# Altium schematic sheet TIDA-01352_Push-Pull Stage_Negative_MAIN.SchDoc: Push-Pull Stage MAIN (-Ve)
size 431 x 279 mm; Date: Not shown in title block; ApprovedBy: Not shown in title block; CheckedBy: Not shown in title block; Author: Not shown in title block; CompanyName: Not shown in title block; DrawnBy: Sanjay Pithadia; Engineer: Sanjay Pithadia; Organization: Not shown in title block; Address1: Not shown in title block; Address2: Not shown in title block; Address3: Not shown in title block; Address4: Not shown in title block; DocumentNumber: 1; Revision: Use project parameter SCH_Rev; SheetNumber: 3; SheetTotal: 9; PageSetup: Record=PageOptions¦CenterHorizontal=True¦CenterVertical=True¦PrintScale=1.00¦XCorrection=1.00¦YCorrection=1.00¦PrintKind=0¦BorderSize=5000000¦LeftOffset=0¦BottomOffset=0¦Orientation=2¦PaperLength=1000¦PaperWidth=1000¦Scale=100¦PaperSource=15¦PrintQuality=600¦MediaType=1¦DitherType=10¦PaperKind=Letter¦PrintScaleMode=1
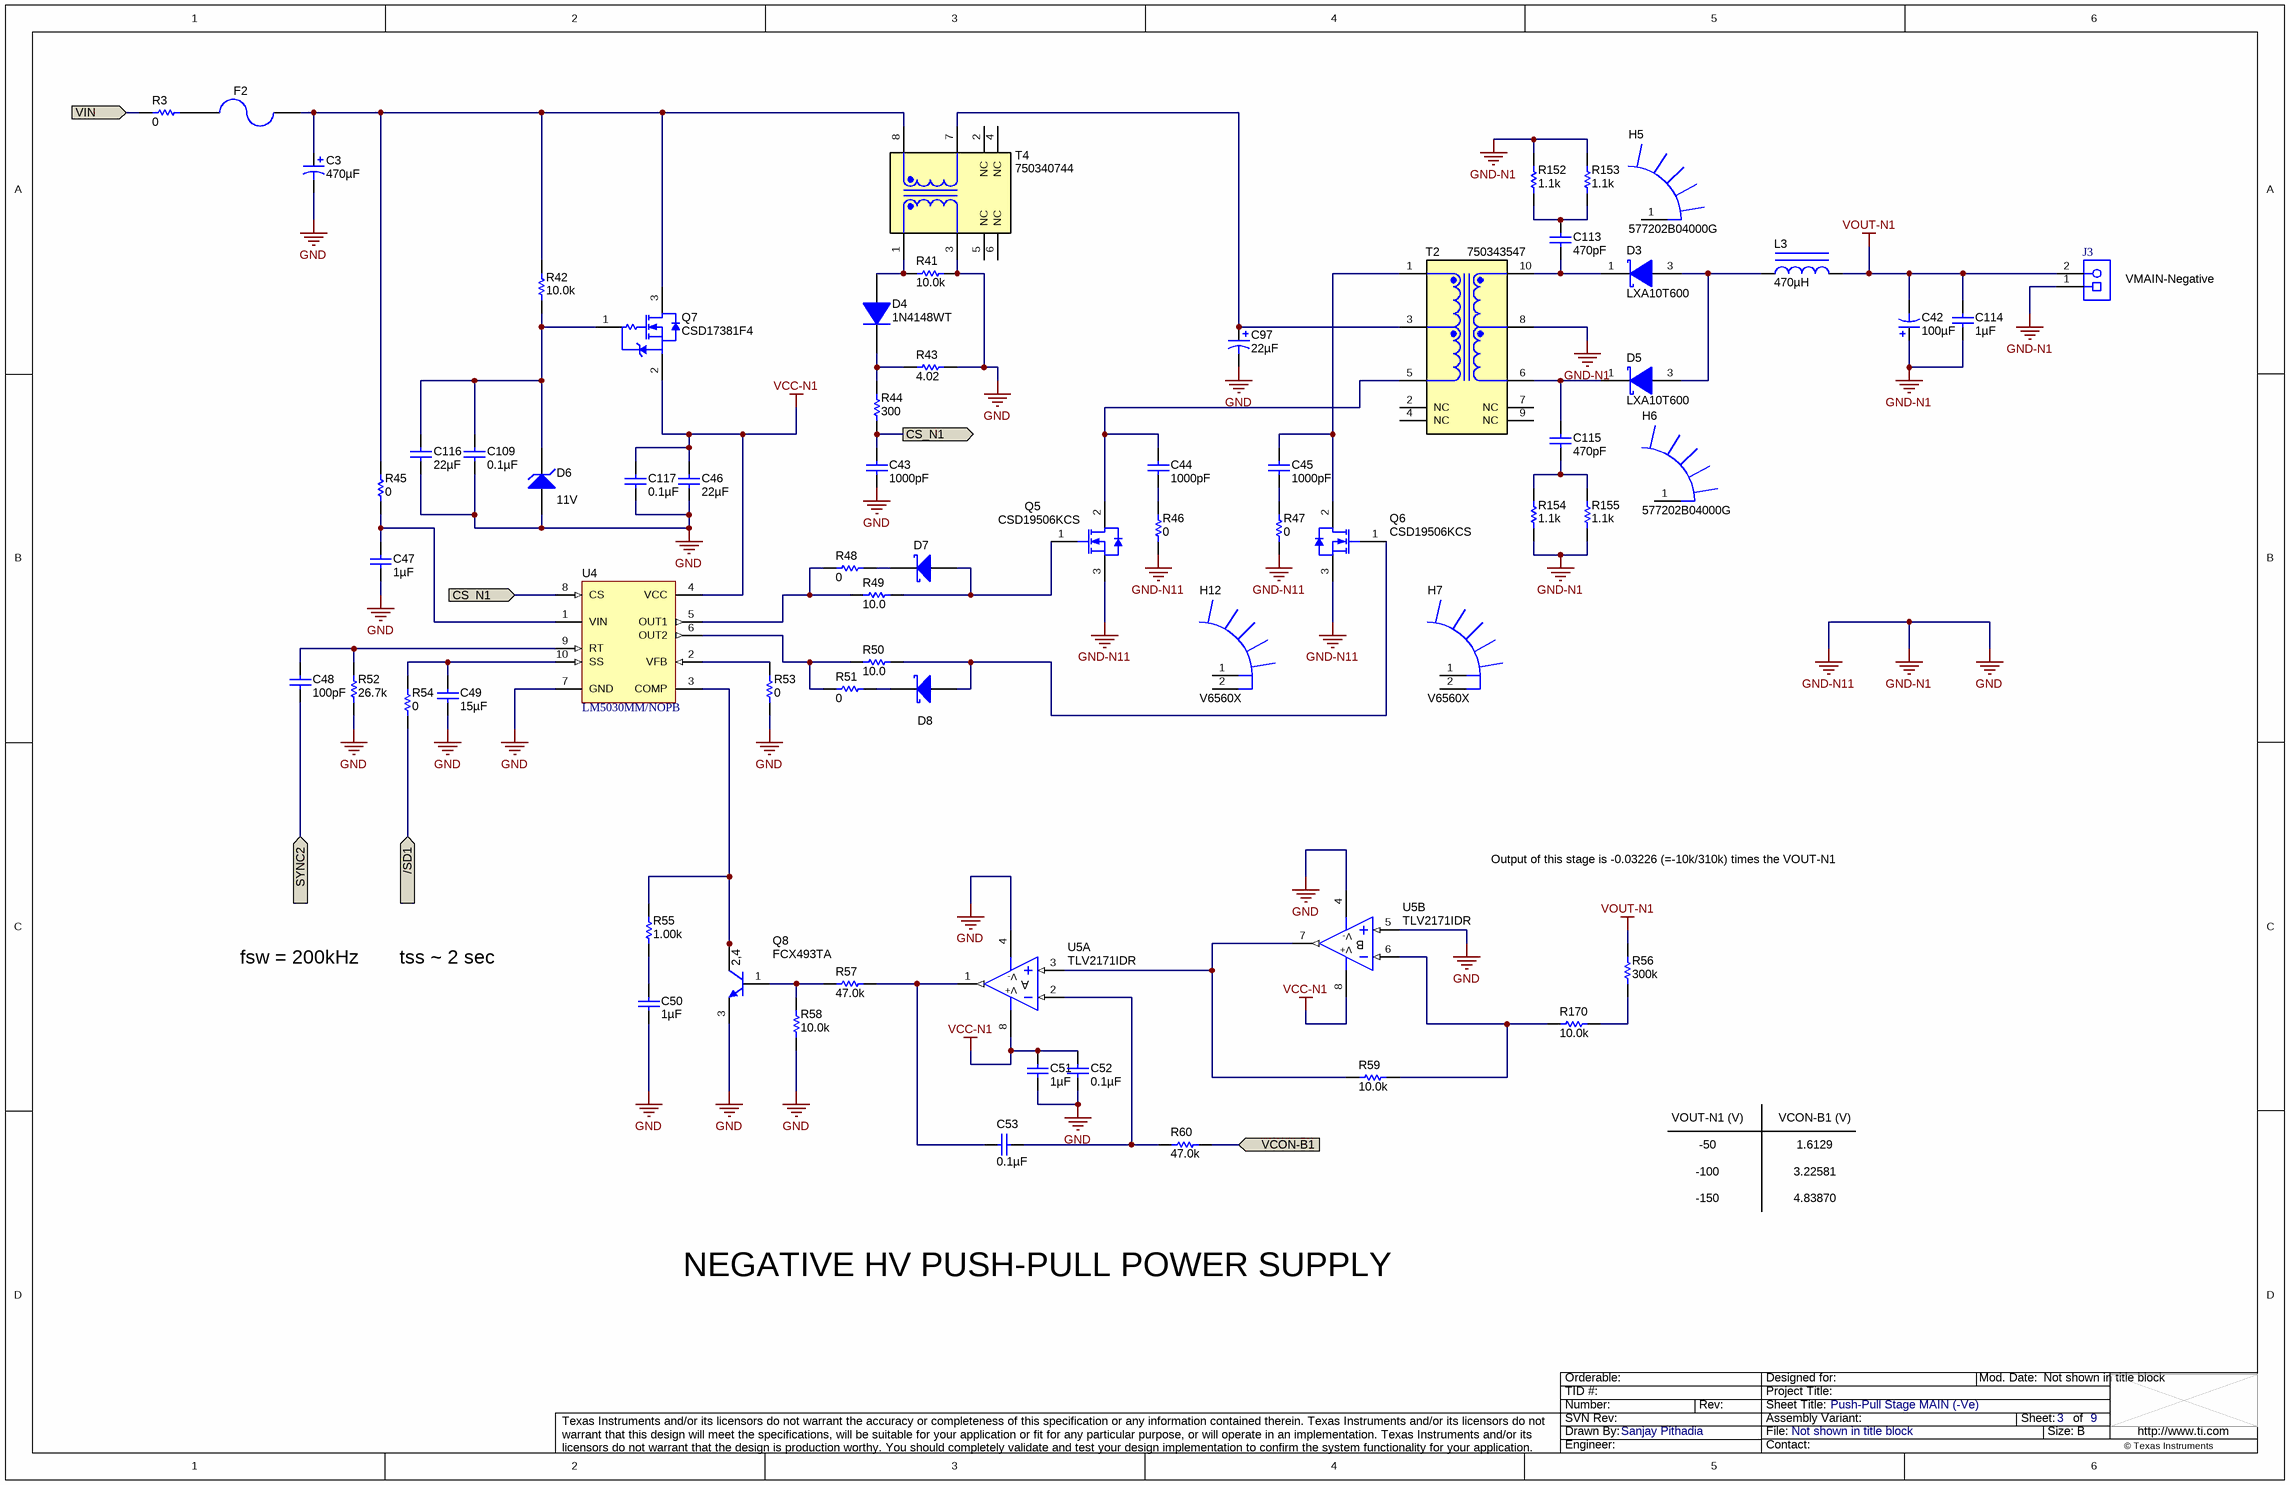
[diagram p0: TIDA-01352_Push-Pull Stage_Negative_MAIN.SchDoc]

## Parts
C3  ValueDisplayed: 470µF  [WCAP-ATLI_1300x3000]  (hidden comment: 860080778023)
C42  ValueDisplayed: 100µF  [Nichicon_2000x3000_Snap]  (hidden comment: LLS2G101MELY)
C43  ValueDisplayed: 1000pF  [0603]  (hidden comment: GRM188R71E102KA01D)
C44  ValueDisplayed: 1000pF  [0603]  (hidden comment: GRM188R71E102KA01D)
C45  ValueDisplayed: 1000pF  [0603]  (hidden comment: GRM188R71E102KA01D)
C46  ValueDisplayed: 22µF  [1210_280]  (hidden comment: 12103D226MAT2A)
C47  ValueDisplayed: 1µF  [0805_HV]  (hidden comment: 08055C105KAT2A)
C48  ValueDisplayed: 100pF  [0603]  (hidden comment: 06035A101FAT2A)
C49  ValueDisplayed: 15µF  [0805_HV]  (hidden comment: C2012X5R1V156M125AC)
C50  ValueDisplayed: 1µF  [0603]  (hidden comment: GMK107BJ105KA-T)
C51  ValueDisplayed: 1µF  [0805_HV]  (hidden comment: 08055C105KAT2A)
C52  ValueDisplayed: 0.1µF  [0603]  (hidden comment: 06035C104KAT2A)
C53  ValueDisplayed: 0.1µF  [0603]  (hidden comment: 06035C104KAT2A)
C97  ValueDisplayed: 22µF  [SM_RADIAL_E]  (hidden comment: EEE-FC1H220P)
C109  ValueDisplayed: 0.1µF  [0603]  (hidden comment: 06035C104KAT2A)
C113  ValueDisplayed: 470pF  [1206]  (hidden comment: VJ1206Y471KBEAT4X)
C114  ValueDisplayed: 1µF  [2220_200]  (hidden comment: GRM55DR72E105KW01L)
C115  ValueDisplayed: 470pF  [1206]  (hidden comment: VJ1206Y471KBEAT4X)
C116  ValueDisplayed: 22µF  [1210_280]  (hidden comment: 12103D226MAT2A)
C117  ValueDisplayed: 0.1µF  [0603]  (hidden comment: 06035C104KAT2A)
D3  LXA10T600  [TO-220AC]
D4  1N4148WT  [Fairchild_SOD-523F]
D5  LXA10T600  [TO-220AC]
D6  value 11V  [SMA]  (hidden comment: 1SMA5926BT3G)
D7  PMEG1030EJ,115  [SOD-323F]  (value not drawn)
D8  PMEG1030EJ,115  [SOD-323F]  (value not drawn)
F2  0678L9150-02  [Fuse_0678L]  (value not drawn)
H5  577202B04000G  [Aavid_577202B04000G]
H6  577202B04000G  [Aavid_577202B04000G]
H7  V6560X  [ASMN_V6560X]
H12  V6560X  [ASMN_V6560X]
J3  1727010  [PhoenixConact_1727010]  (value not drawn)
L3  ValueDisplayed: 470µH  [1447440C]  (hidden comment: 1447440C)
Q5  CSD19506KCS  [KCS0003B]
Q6  CSD19506KCS  [KCS0003B]
Q7  CSD17381F4  [YJC0003A]
Q8  FCX493TA  [SOT-89-3]
R3  ValueDisplayed: 0  [5108]  (hidden comment: 5108)
R41  ValueDisplayed: 10.0k  [0603]  (hidden comment: CRCW060310K0FKEA)
R42  ValueDisplayed: 10.0k  [0603]  (hidden comment: CRCW060310K0FKEA)
R43  ValueDisplayed: 4.02  [0805_HV]  (hidden comment: CRCW08054R02FKEA)
R44  ValueDisplayed: 300  [0603]  (hidden comment: RC0603FR-07300RL)
R45  ValueDisplayed: 0  [0603]  (hidden comment: CRCW06030000Z0EA)
R46  ValueDisplayed: 0  [0603]  (hidden comment: CRCW06030000Z0EA)
R47  ValueDisplayed: 0  [0603]  (hidden comment: CRCW06030000Z0EA)
R48  ValueDisplayed: 0  [0603]  (hidden comment: CRCW06030000Z0EA)
R49  ValueDisplayed: 10.0  [0603]  (hidden comment: CRCW060310R0FKEA)
R50  ValueDisplayed: 10.0  [0603]  (hidden comment: CRCW060310R0FKEA)
R51  ValueDisplayed: 0  [0603]  (hidden comment: CRCW06030000Z0EA)
R52  ValueDisplayed: 26.7k  [0603]  (hidden comment: CRCW060326K7FKEA)
R53  ValueDisplayed: 0  [0603]  (hidden comment: CRCW06030000Z0EA)
R54  ValueDisplayed: 0  [0603]  (hidden comment: CRCW06030000Z0EA)
R55  ValueDisplayed: 1.00k  [0603]  (hidden comment: CRCW06031K00FKEA)
R56  ValueDisplayed: 300k  [1206]  (hidden comment: RC1206FR-07300KL)
R57  ValueDisplayed: 47.0k  [0603]  (hidden comment: RC0603FR-0747KL)
R58  ValueDisplayed: 10.0k  [0603]  (hidden comment: CRCW060310K0FKEA)
R59  ValueDisplayed: 10.0k  [1206]  (hidden comment: CRCW120610K0FKEA)
R60  ValueDisplayed: 47.0k  [0603]  (hidden comment: RC0603FR-0747KL)
R152  ValueDisplayed: 1.1k  [PR01]  (hidden comment: PR01000101101JR500)
R153  ValueDisplayed: 1.1k  [PR01]  (hidden comment: PR01000101101JR500)
R154  ValueDisplayed: 1.1k  [PR01]  (hidden comment: PR01000101101JR500)
R155  ValueDisplayed: 1.1k  [PR01]  (hidden comment: PR01000101101JR500)
R170  ValueDisplayed: 10.0k  [1206]  (hidden comment: CRCW120610K0FKEA)
T2  750343547  [Wurth_750343473]
T4  750340744  [Wurth_750340744]
U4  LM5030MM/NOPB  [MUB10A_N]
U5  TLV2171IDR  [D0008A_N]  (parts A,B of 2)

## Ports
/SD1 (in), CS_N1 (in), CS_N1 (out), SYNC2 (in), VCON-B1 (in), VIN (in)

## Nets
GND: C3.2(-) C42.1(+) C43.2 C46.2 C47.2 C49.2 C50.2 C51.2 C52.2 C97.2(-) C109.2 C114.2 C116.2 C117.2 D6.2(A) J3.1 Q5.3(S) Q6.3(S) Q8.3(E) R41.1 R43.2 R46.2 R47.2 R52.1 R53.1 R58.1 R152.2 R153.2 R154.1 R155.1 T2.8 T4.3 U4.7(GND) U5.4(V-) U5.5(IN+)  [also labelled GND-N1, GND-N11]
VCC-N1: C46.1 C51.1 C52.1 C117.1 Q7.2(S) U4.4(VCC) U5.8(V+)
VOUT-N1: C42.2(-) C114.1 J3.2 L3.2 R56.2
/SD1: R54.1 ; port /SD1
CS_N1: C43.1 R44.1 U4.8(CS) ; port CS_N1
SYNC2: C48.2 ; port SYNC2
VCON-B1: R60.2 ; port VCON-B1
VIN: R3.1 ; port VIN
NetC3_1: C3.1(+) F2.1 Q7.3(D) R42.2 R45.2 T4.8
NetC44_1: C44.1 Q5.2(D) T2.5
NetC44_2: C44.2 R46.1
NetC45_1: C45.1 Q6.2(D) T2.1
NetC45_2: C45.2 R47.1
NetC47_1: C47.1 R45.1 U4.1(VIN)
NetC48_1: C48.1 R52.2 U4.9(RT)
NetC49_1: C49.1 R54.2 U4.10(SS)
NetC50_1: C50.1 R55.1
NetC53_1: C53.1 R60.1 U5.2(IN-)
NetC53_2: C53.2 R57.2 U5.1(OUT)
NetC97_1: C97.1(+) T2.3 T4.7
NetC109_1: C109.1 C116.1 D6.1(K) Q7.1(G) R42.1
NetC113_1: C113.1 R152.1 R153.1
NetC113_2: C113.2 D3.1(A) T2.10
NetC115_1: C115.1 D5.1(A) T2.6
NetC115_2: C115.2 R154.2 R155.2
NetD3_3: D3.3(K) D5.3(K) L3.1
NetD4_1: D4.1(K) R43.1 R44.2
NetD4_2: D4.2(A) R41.2 T4.1
NetD7_1: D7.1(K) R48.1
NetD7_2: D7.2(A) Q5.1(G) R49.2
NetD8_1: D8.1(K) R51.1
NetD8_2: D8.2(A) Q6.1(G) R50.2
NetF2_2: F2.2 R3.2
NetQ8_1: Q8.1(B) R57.1 R58.2
NetQ8_2: Q8.2(C) Q8.4(C) R55.2 U4.3(COMP)
NetR48_2: R48.2 R49.1 U4.5(OUT1)
NetR50_1: R50.1 R51.2 U4.6(OUT2)
NetR53_2: R53.2 U4.2(VFB)
NetR56_1: R56.1 R170.1
NetR59_1: R59.1 U5.3(IN+) U5.7(OUT)
NetR59_2: R59.2 R170.2 U5.6(IN-)

Not connected (* = marked no-connect by the designer): H5 1; H6 1; H7 1 2; H12 1 2; T2 2(NC) 4(NC) 7(NC) 9(NC); T4 2(NC) 4(NC) 5(NC) 6(NC)

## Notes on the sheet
- (near J3) VMAIN-Negative
- Output of this stage is -0.03226 (=-10k/310k) times the VOUT-N1
- fsw = 200kHz
- tss ~ 2 sec
- VOUT-N1 (V)
- -50
- -100
- VCON-B1 (V)
- 1.6129
- 3.22581
- -150
- 4.83870
- NEGATIVE HV PUSH-PULL POWER SUPPLY

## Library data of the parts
C3 = 860080778023: CAP, AL, 470 µF, 63 V, +/- 20%, TH; Manufacturer: Wurth Elektronik; Polarized: Y; CompType: Capacitor; Value: 470uF; U/M: EA; Cap_F: 0.00047; Tolerance_%: 20; Value1: Unknown; VDC_V: 63; Value2: 63V; IRMS_A: 2.225; TaMin_C: -55; TaMax_C: 105; Cap_Case: 13x30mm; SizeAreaWB_mm2: 225; SizeArea_mm2: 169; SizeX_mm: 13; SizeZ_mm: 31.5; AEC Category: Q200; AEC Qualified: N
C42 = LLS2G101MELY: CAP, AL, 100 µF, 400 V, +/- 20%, TH; Manufacturer: Nichicon; Polarized: Y; CompType: Capacitor; Value: 100uF; U/M: EA; Cap_F: 0.0001; Tolerance_%: 20; Value1: Unknown; VDC_V: 400; Value2: 400V; IRMS_A: 0.95; TaMin_C: -25; TaMax_C: 85; Cap_Case: 20x30mm; SizeAreaWB_mm2: 484; SizeZ_mm: 32; AEC Category: Q200; AEC Qualified: N
C43-C45 = GRM188R71E102KA01D: CAP, CERM, 1000 pF, 25 V, +/- 10%, X7R, 0603; Manufacturer: MuRata; Polarized: N; CompType: Capacitor; Value: 1000pF; U/M: EA; Cap_F: 0.000000001; Tolerance_%: 10; Value1: Unknown; VDC_V: 25; Value2: 25V; TaMin_C: -55; TaMax_C: 125; SizeArea_mm2: 1.28; SizeAreaWB_mm2: 4.68; SizeX_mm: 1.6; SizeY_mm: 0.8; SizeZ_mm: 1; AEC Category: Q200
C46 C116 = 12103D226MAT2A: CAP, CERM, 22 µF, 25 V, +/- 20%, X5R, 1210; Manufacturer: AVX; Polarized: N; CompType: Capacitor; Value: 22uF; U/M: EA; Cap_F: 0.000022; Tolerance_%: 20; Value1: Unknown; VDC_V: 25; Value2: 25V; TaMin_C: -55; TaMax_C: 85; Cap_Case: 1210; SizeArea_mm2: 8; SizeAreaWB_mm2: 14.7; SizeX_mm: 3.2; SizeY_mm: 2.5; SizeZ_mm: 2.8; AEC Category: Q200
C47 C51 = 08055C105KAT2A: CAP, CERM, 1 µF, 50 V, +/- 10%, X7R, 0805; Manufacturer: AVX; Polarized: N; CompType: Capacitor; Value: 1uF; U/M: EA; Cap_F: 0.000001; Tolerance_%: 10; Value1: Unknown; VDC_V: 50; Value2: 50V; TaMin_C: -55; TaMax_C: 125; Cap_Case: 0805; SizeArea_mm2: 2.5; SizeAreaWB_mm2: 6.75; SizeX_mm: 2; SizeY_mm: 1.25; SizeZ_mm: 1.45; AEC Category: Q200
C48 = 06035A101FAT2A: CAP, CERM, 100 pF, 50 V, +/- 1%, C0G/NP0, 0603; Manufacturer: AVX; Polarized: N; CompType: Capacitor; Value: 100pF; U/M: EA; Cap_F: 0.0000000001; Tolerance_%: 1; Value1: Unknown; VDC_V: 50; Value2: 50V; TaMin_C: -55; TaMax_C: 125; SizeArea_mm2: 1.28; SizeAreaWB_mm2: 4.68; SizeX_mm: 1.6; SizeY_mm: 0.8; AEC Category: Q200
C49 = C2012X5R1V156M125AC: CAP, CERM, 15 µF, 35 V, +/- 20%, X5R, 0805; Manufacturer: TDK; Polarized: N; CompType: Capacitor; Value: 15uF; U/M: EA; Cap_F: 0.000015; Tolerance_%: 20; ESR_ohm: 0.001669; Value1: 0.001669 ohm; VDC_V: 35; Value2: 35V; IRMS_A: 5.04984; TaMin_C: -55; TaMax_C: 85; Cap_Case: 0805; SizeArea_mm2: 2.5; SizeAreaWB_mm2: 6.75; SizeX_mm: 2; SizeY_mm: 1.25; SizeZ_mm: 1.45; AEC Category: Q200
C50 = GMK107BJ105KA-T: CAP, CERM, 1 µF, 35 V, +/- 10%, X5R, 0603; Manufacturer: Taiyo Yuden; Polarized: N; CompType: Capacitor; Value: 1uF; U/M: EA; Cap_F: 0.000001; Tolerance_%: 10; Value1: Unknown; VDC_V: 35; Value2: 35V; TaMin_C: -55; TaMax_C: 85; SizeArea_mm2: 1.28; SizeAreaWB_mm2: 4.68; SizeX_mm: 1.6; SizeY_mm: 0.8; SizeZ_mm: 1; AEC Category: Q200
C52 C53 C109 C117 = 06035C104KAT2A: CAP, CERM, 0.1 µF, 50 V, +/- 10%, X7R, 0603; Manufacturer: AVX; Polarized: N; CompType: Capacitor; Value: 0.1uF; U/M: EA; Cap_F: 0.0000001; Tolerance_%: 10; Value1: Unknown; VDC_V: 50; Value2: 50V; TaMin_C: -55; TaMax_C: 125; SizeArea_mm2: 1.28; SizeAreaWB_mm2: 4.68; SizeX_mm: 1.6; SizeY_mm: 0.8; SizeZ_mm: 1; AEC Category: Q200
C97 = EEE-FC1H220P: CAP, AL, 22 µF, 50 V, +/- 20%, 0.7 ohm, SMD; Manufacturer: Panasonic; Polarized: Y; CompType: Capacitor; Value: 22uF; U/M: EA; Cap_F: 0.000022; Tolerance_%: 20; Value1: 0.7 ohm; VDC_V: 50; Value2: 50V; ESR_ohm: 0.7; IRMS_A: 0.12; TaMin_C: -40; TaMax_C: 105; Cap_Case: E; SizeAreaWB_mm2: 118.45; SizeArea_mm2: 78.85; SizeX_mm: 9.5; SizeY_mm: 8.3; SizeZ_mm: 6.2; AEC Category: Q200
C113 C115 = VJ1206Y471KBEAT4X: CAP, CERM, 470 pF, 500 V, +/- 10%, X7R, 1206; Manufacturer: Vishay-Vitramon; Polarized: N; CompType: Capacitor; Value: 470pF; U/M: EA; Cap_F: 0.00000000047; Tolerance_%: 10; Value1: Unknown; VDC_V: 500; Value2: 500V; TaMin_C: -55; TaMax_C: 125; SizeArea_mm2: 5.12; SizeAreaWB_mm2: 10.92; SizeX_mm: 3.2; SizeY_mm: 1.6; SizeZ_mm: 1.35; AEC Category: Q200
C114 = GRM55DR72E105KW01L: CAP, CERM, 1 µF, 250 V, +/- 10%, X7R, 2220; Manufacturer: MuRata; Polarized: N; CompType: Capacitor; Value: 1uF; U/M: EA; Cap_F: 0.000001; Tolerance_%: 10; ESR_ohm: 0.007086; Value1: 0.007086 ohm; VDC_V: 250; Value2: 250V; IRMS_A: 2.0605; TaMin_C: -55; TaMax_C: 125; Cap_Case: 2220; SizeArea_mm2: 28.5; SizeAreaWB_mm2: 53.9; SizeX_mm: 5.7; SizeY_mm: 5; SizeZ_mm: 2; AEC Category: Q200
D3 D5 = LXA10T600: Diode, Schottky, 600 V, 10 A, TH; Manufacturer: Power Integrations; SymbolCreator: a0412235; U/M: EA; Vf_V: 2.4; Value: 600V; Value1: 10A; Value2: 2.4V; Io_A: 10; Vr_V: 600; TJmax_C: 150; RJC_CperW: 1.4; SizeAreaWB_mm2: 78.975; SizeArea_mm2: 45.675; SizeX_mm: 10.15; SizeY_mm: 4.5; SizeZ_mm: 23; AEC Category: Q101; AEC Qualified: N
D4 = 1N4148WT: Diode, Switching, 75 V, 0.3 A, SOD-523F; Manufacturer: Fairchild Semiconductor; U/M: EA; Value: 75V; Value1: 0.3A; Io_A: 0.3; Vr_V: 75; TJmax_C: 150; SizeAreaWB_mm2: 4.68; SizeArea_mm2: 1.28; SizeX_mm: 1.6; SizeY_mm: 0.8; SizeZ_mm: 0.7; AEC Category: Q101
D6 = 1SMA5926BT3G: Diode, Zener, 11 V, 1.5 W, SMA; Manufacturer: ON Semiconductor; SymbolCreator: a0412235; U/M: EA; Power_W: 1.5; Vz_V: 11; Value1: 1.5W; RJA_CperW: 250; SizeAreaWB_mm2: 37.3428; SizeArea_mm2: 16.3228; SizeX_mm: 5.59; SizeY_mm: 2.92; SizeZ_mm: 2.87; AEC Category: Q101
D7 D8 = PMEG1030EJ,115: Diode, Schottky, 10 V, 3 A, SOD-323F; Manufacturer: NXP Semiconductor; U/M: EA; Vf_V: 0.53; Value: 10V; Value1: 3A; Value2: 0.53V; Io_A: 3; Vr_V: 10; TJmax_C: 150; SizeAreaWB_mm2: 7.875; SizeArea_mm2: 3.125; SizeX_mm: 2.5; SizeY_mm: 1.25; SizeZ_mm: 0.8; AEC Category: Q101; AEC Qualified: N
F2 = 0678L9150-02: Fuse, 15 A, 250 VAC, 72 VDC, SMD; Manufacturer: Bel Fuse; SizeAreaWB_mm2: 59.59; SizeArea_mm2: 29.89; SizeX_mm: 9.8; SizeY_mm: 3.05; SizeZ_mm: 3.18; VDC_V: 72; VAC_V: 250; Irating_A: 15; Rtyp_Ohm: 0.0036; MeltingTyp: 110
H5 H6 = 577202B04000G: HEATSINK TO-220 .500" COMPACT; Manufacturer: Aavid; SymbolCreator: a0412235
H7 H12 = V6560X: HEATSINK, ALUM, ANOD, for TO-220; Manufacturer: Assman WSW; SymbolCreator: a0799628
J3 = 1727010: Conn Term Block, 2POS, 3.81mm, TH; Manufacturer: Phoenix Contact; SymbolCreator: a0412235; CompType: Terminal Block
L3 = 1447440C: Inductor, Wirewound, 470 µH, 4 A, 0.125 ohm, TH; Manufacturer: MuRata; Value: 470uH; Ind_H: 470.0E-6; Imax_A: 4; Irms: 4A @ 50C rise; Isat: 4A @ 40% inductance drop; DCR_ohm: 0.125; Value2: 4A; SizeAreaWB_mm2: 1071.66; SizeArea_mm2: 944.66; SizeX_mm: 31.7; SizeY_mm: 29.8; SizeZ_mm: 23.5; AEC Category: Q200; AEC Qualified: N
Q5 Q6 = CSD19506KCS: MOSFET, N-CH, 80 V, 100 A, KCS0003B (TO-220-3); Manufacturer: Texas Instruments; Alternate Manufacturer: None; U/M: EA; ChType: N; Value: 80V; VdsMax_V: 80; Value1: ? ohm; Value2: 120 nC; QgTyp_nC: 120; Vgs_V: 20; IdsMax_A: 100; SizeAreaWB_mm2: 79.648; SizeArea_mm2: 46.228; SizeX_mm: 4.55; SizeY_mm: 10.16; SizeZ_mm: 20.45; AEC Category: Q101
Q7 = CSD17381F4: MOSFET, N-CH, 30 V, 3.1 A, YJC0003A (PICOSTAR-3); Manufacturer: Texas Instruments; Alternate Manufacturer: None; SymbolCreator: a0411947; U/M: EA; ChType: N; Value: 30V; VdsMax_V: 30; Value1: 0.09 ohm; Rdson45_ohm: 0.09; Value2: 1.04 nC; QgTyp_nC: 1.04; Vgs_V: 12; IdsMax_A: 3.1; SizeAreaWB_mm2: 3.327225; SizeArea_mm2: 0.657225; SizeX_mm: 1.035; SizeY_mm: 0.635; SizeZ_mm: 0.35; AEC Category: Q101
Q8 = FCX493TA, Diodes Inc.: Transistor, NPN, 100 V, 1 A, SOT-89; SymbolCreator: a0412235; PNP: 0; NPN: 1; Vceo_V: 100; Vcesat1_V: 0.6; Value: 100 V; Value1: 1 A; HfeMax: 300; TaMin_C: -65; TaMax_C: 150; CompType: BJT; U/M: EA; AEC Category: Q101; SizeAreaWB_mm2: 28.05; SizeArea_mm2: 18.45; SizeX_mm: 4.1; SizeY_mm: 4.5; SizeZ_mm: 1.5
R3 = 5108: RES, 0, 1%, 0.5 W, 1206; Manufacturer: Keystone; CompType: Resistor; Value: 0; Tolerance_%: 1; Power_W: 0.5; Value2: 0.5W; TempCo: ppm/C; SizeArea_mm2: 5.185; SizeX_mm: 3.05; SizeY_mm: 1.7; SizeZ_mm: 0.84; U/M: EA; AEC Category: Q200; AEC Qualified: N
R41 R42 R58 = CRCW060310K0FKEA: RES, 10.0 k, 1%, 0.1 W, 0603; Manufacturer: Vishay-Dale; CompType: Resistor; Value: 10.0k; Res_ohm: 10000; Value_Code: 10k0; Tolerance_%: 1; Power_W: 0.1; Value2: 0.1W; VDC_V: 75; TempCo: 100 ppm/C; SizeArea_mm2: 1.28; SizeX_mm: 1.6; SizeY_mm: 0.8; EIA_Code: E96; U/M: EA; AEC Category: Q200
R43 = CRCW08054R02FKEA: RES, 4.02, 1%, 0.125 W, 0805; Manufacturer: Vishay-Dale; CompType: Resistor; Value: 4.02; Value_Code: 4R02; Tolerance_%: 1; Power_W: 0.125; Value2: 0.125W; VDC_V: 150; TempCo: 100 ppm/C; SizeArea_mm2: 2.5; SizeX_mm: 2; SizeY_mm: 1.25; SizeZ_mm: 1.45; EIA_Code: E96; U/M: EA; AEC Category: Q200
R44 = RC0603FR-07300RL: RES, 300, 1%, 0.1 W, 0603; Manufacturer: Yageo America; CompType: Resistor; Value: 300; Value_Code: 300R; Tolerance_%: 1; Power_W: 0.1; Value2: 0.1W; VDC_V: 150; TempCo: 200 ppm/C; SizeArea_mm2: 1.28; SizeX_mm: 1.6; SizeY_mm: 0.8; U/M: EA; AEC Category: Q200
R45-R48 R51 R53 R54 = CRCW06030000Z0EA: RES, 0, 5%, 0.1 W, 0603; Manufacturer: Vishay-Dale; CompType: Resistor; Value: 0; Value_Code: 0000; Tolerance_%: 5; Power_W: 0.1; Value2: 0.1W; VDC_V: 75; TempCo: 200 ppm/C; SizeArea_mm2: 1.28; SizeX_mm: 1.6; SizeY_mm: 0.8; SizeZ_mm: 1; EIA_Code: E24; U/M: EA; AEC Category: Q200
R49 R50 = CRCW060310R0FKEA: RES, 10.0, 1%, 0.1 W, 0603; Manufacturer: Vishay-Dale; CompType: Resistor; Value: 10.0; Res_ohm: 10; Value_Code: 10R0; Tolerance_%: 1; Power_W: 0.1; Value2: 0.1W; VDC_V: 75; TempCo: 100 ppm/C; SizeArea_mm2: 1.28; SizeX_mm: 1.6; SizeY_mm: 0.8; EIA_Code: E96; U/M: EA; AEC Category: Q200
R52 = CRCW060326K7FKEA: RES, 26.7 k, 1%, 0.1 W, 0603; Manufacturer: Vishay-Dale; CompType: Resistor; Value: 26.7k; Res_ohm: 26700; Value_Code: 26k7; Tolerance_%: 1; Power_W: 0.1; Value2: 0.1W; VDC_V: 75; TempCo: 100 ppm/C; SizeArea_mm2: 1.28; SizeX_mm: 1.6; SizeY_mm: 0.8; EIA_Code: E96; U/M: EA; AEC Category: Q200
R55 = CRCW06031K00FKEA: RES, 1.00 k, 1%, 0.1 W, 0603; Manufacturer: Vishay-Dale; CompType: Resistor; Value: 1.00k; Res_ohm: 1000; Value_Code: 1k00; Tolerance_%: 1; Power_W: 0.1; Value2: 0.1W; VDC_V: 75; TempCo: 100 ppm/C; SizeArea_mm2: 1.28; SizeX_mm: 1.6; SizeY_mm: 0.8; EIA_Code: E96; U/M: EA; AEC Category: Q200
R56 = RC1206FR-07300KL: RES, 300 k, 1%, 0.25 W, 1206; Manufacturer: Yageo America; CompType: Resistor; Value: 300k; Res_ohm: 300000; Tolerance_%: 1; Power_W: 0.25; Value2: 0.25W; VDC_V: 200; TempCo: 100 ppm/C; SizeArea_mm2: 5.12; SizeX_mm: 3.2; SizeY_mm: 1.6; SizeZ_mm: 1.35; U/M: EA; AEC Category: Q200
R57 R60 = RC0603FR-0747KL: RES, 47.0 k, 1%, 0.1 W, 0603; Manufacturer: Yageo America; CompType: Resistor; Value: 47.0k; Res_ohm: 47000; Value_Code: 47k0; Tolerance_%: 1; Power_W: 0.1; Value2: 0.1W; VDC_V: 150; TempCo: 200 ppm/C; SizeArea_mm2: 1.28; SizeX_mm: 1.6; SizeY_mm: 0.8; U/M: EA; AEC Category: Q200
R59 R170 = CRCW120610K0FKEA: RES, 10.0 k, 1%, 0.25 W, 1206; Manufacturer: Vishay-Dale; CompType: Resistor; Value: 10.0k; Res_ohm: 10000; Value_Code: 10k0; Tolerance_%: 1; Power_W: 0.25; Value2: 0.25W; VDC_V: 200; TempCo: 100 ppm/C; SizeArea_mm2: 5.12; SizeX_mm: 3.2; SizeY_mm: 1.6; SizeZ_mm: 1.35; EIA_Code: E96; U/M: EA; AEC Category: Q200; Green_Lifecycle: Active; Green_REACh: Passed
R152-R155 = PR01000101101JR500: RES, 1.1 k, 5%, 1 W, AEC-Q200 Grade 0, D2.5xL6.5mm; Manufacturer: Vishay-Bccomponents; CompType: Resistor; Value: 1.1k; Res_ohm: 1100; Value_Code: 1k10; Tolerance_%: 5; Power_W: 1; Value2: 1W; VDC_V: 350; TempCo: 250 ppm/C; EIA_Code: E24; U/M: EA; AEC Category: Q200; AEC Qualified: Y; AEC Grade: 0
T2 = 750343547: Transformer, 100 uH, TH; Manufacturer: Wurth Elektronik; SymbolCreator: Altium; ValueDisplayed: 100µH; Value: 100uH; DCR_ohm: 0.025; Lp: 100; Ind_H: 0.0001; Ns1toNp: 7.5; Rsec1_ohm: 0.27; Rsec2_ohm: 0.37; SizeAreaWB_mm2: 934.4274; SizeArea_mm2: 816.1274; SizeX_mm: 29.21; SizeY_mm: 27.94; SizeZ_mm: 21.59
T4 = 750340744: Transformer, TH; Manufacturer: Wurth Elektronik; SymbolCreator: Altium; ValueDisplayed: 2mH; Value: 2mH; Lp: 2000; Ns1toNp: 100; Rs1: 5.87; SizeAreaWB_mm2: 94.9181; SizeArea_mm2: 59.9181; SizeX_mm: 8.13; SizeY_mm: 7.37; SizeZ_mm: 5.46
U4 = LM5030MM/NOPB: 100V Push-Pull Current Mode PWM Controller, 10-pin MSOP, Pb-Free; Manufacturer: Texas Instruments; PackageTopMarking: ZXTT*S73B; PowerWise: Y; CompType: Switcher
U5 = TLV2171IDR: 36-V, Single-Supply, Low-Power Operational Amplifier for Cost-Sensitive Systems, D0008A (SOIC-8); Manufacturer: Texas Instruments; CompType: IC; SizeArea_mm2: 30.38; SizeAreaWB_mm2: 56.58; SizeX_mm: 4.9; SizeY_mm: 6.2; SizeZ_mm: 1.75; U/M: EA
